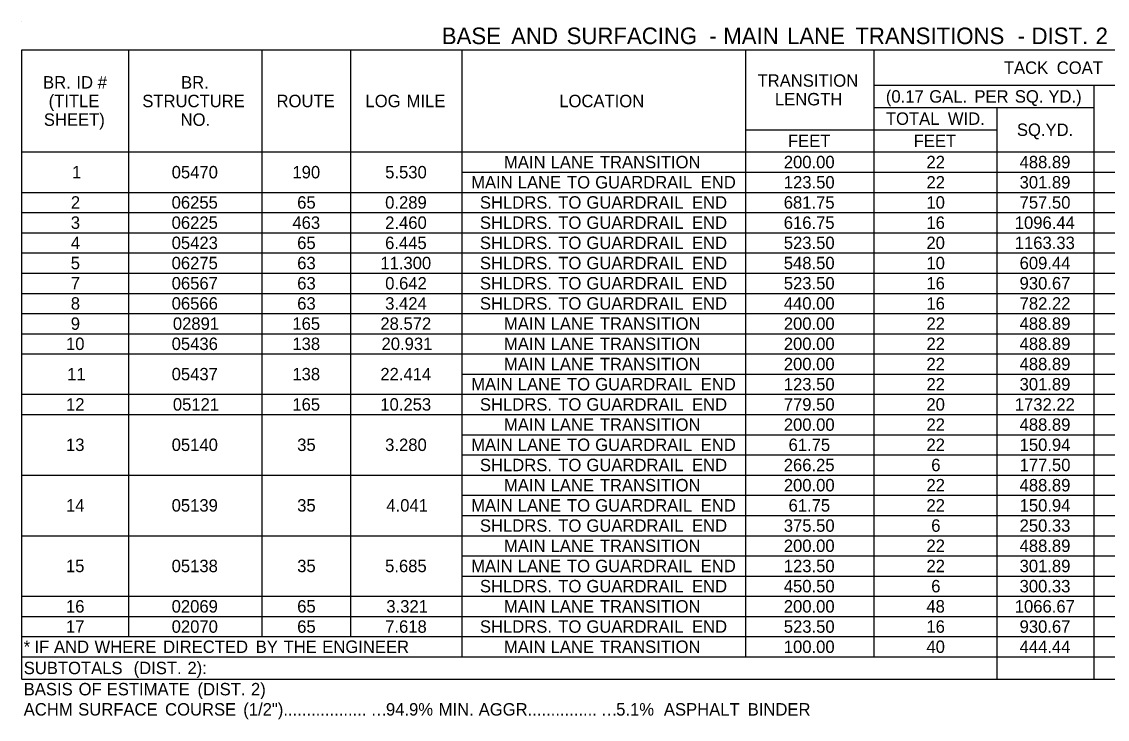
# Model space of a CAD drawing. Extents: x 544250 to 1930787, y -1948365 to 596640.
# Drawn here: x 552201 to 552725, y -1946541 to -1946204 of the extents above; entities that cross this region are included whole.
import ezdxf

# ---------------------------------------------------------------- set-up
doc = ezdxf.new("R2010")
doc.units = 0
doc.layers.add('Default', color=7, linetype='Continuous')

msp = doc.modelspace()

# ---------------------------------------------------------------- linework, layer by layer
at = {"layer": 'Default'}
for p, q in [((552201.23, -1946203.88), (552201.23, -1946203.88)), ((552201.23, -1946217.53), (552997.32, -1946217.53)), ((552201.23, -1946521.24), (552201.23, -1946217.53)), ((552252.9, -1946266.77), (552252.9, -1946217.53)), ((552317.25, -1946266.77), (552317.25, -1946217.53)), ((552360.15, -1946266.77), (552360.15, -1946217.53)), ((552413.78, -1946510.52), (552413.78, -1946217.53)), ((552550.77, -1946510.52), (552550.77, -1946217.53)), ((552612.68, -1946510.52), (552612.68, -1946217.53)), ((552612.68, -1946234.59), (552612.68, -1946217.53)), ((552612.68, -1946234.59), (552997.32, -1946234.59)), ((552718.95, -1946245.32), (552718.95, -1946234.59)), ((552718.95, -1946521.24), (552718.95, -1946234.59)), ((552612.68, -1946245.32), (552718.95, -1946245.32)), ((552672.15, -1946521.24), (552672.15, -1946245.32)), ((552550.77, -1946256.04), (552612.68, -1946256.04)), ((552550.77, -1946256.04), (552672.15, -1946256.04)), ((552672.15, -1946266.77), (552672.15, -1946256.04)), ((552201.23, -1946266.77), (552672.15, -1946266.77)), ((552201.23, -1946266.77), (552413.78, -1946266.77)), ((552252.9, -1946500.77), (552252.9, -1946266.77)), ((552317.25, -1946500.77), (552317.25, -1946266.77)), ((552360.15, -1946500.77), (552360.15, -1946266.77)), ((552413.78, -1946266.77), (552997.32, -1946266.77)), ((552672.15, -1946266.77), (552838.88, -1946266.77)), ((552413.78, -1946276.52), (552997.32, -1946276.52)), ((552201.23, -1946286.27), (552997.32, -1946286.27)), ((552201.23, -1946286.27), (552997.32, -1946286.27)), ((552201.23, -1946296.02), (552997.32, -1946296.02)), ((552201.23, -1946296.02), (552997.32, -1946296.02)), ((552201.23, -1946305.77), (552997.32, -1946305.77)), ((552201.23, -1946305.77), (552997.32, -1946305.77)), ((552201.23, -1946315.52), (552997.32, -1946315.52)), ((552201.23, -1946315.52), (552997.32, -1946315.52)), ((552201.23, -1946325.27), (552997.32, -1946325.27)), ((552201.23, -1946325.27), (552997.32, -1946325.27)), ((552201.23, -1946335.02), (552997.32, -1946335.02)), ((552201.23, -1946335.02), (552997.32, -1946335.02)), ((552201.23, -1946344.77), (552997.32, -1946344.77)), ((552201.23, -1946344.77), (552997.32, -1946344.77)), ((552201.23, -1946354.52), (552997.32, -1946354.52)), ((552201.23, -1946364.27), (552997.32, -1946364.27)), ((552672.15, -1946364.27), (552997.32, -1946364.27)), ((552413.78, -1946374.02), (552672.15, -1946374.02)), ((552672.15, -1946374.02), (552997.32, -1946374.02)), ((552201.23, -1946383.77), (552997.32, -1946383.77)), ((552201.23, -1946383.77), (552997.32, -1946383.77)), ((552201.23, -1946393.52), (552997.32, -1946393.52)), ((552201.23, -1946393.52), (552997.32, -1946393.52)), ((552413.78, -1946403.27), (552997.32, -1946403.27)), ((552413.78, -1946413.02), (552997.32, -1946413.02)), ((552201.23, -1946422.77), (552997.32, -1946422.77)), ((552201.23, -1946422.77), (552997.32, -1946422.77)), ((552413.78, -1946432.52), (552997.32, -1946432.52)), ((552413.78, -1946442.27), (552997.32, -1946442.27)), ((552201.23, -1946452.02), (552997.32, -1946452.02)), ((552201.23, -1946452.02), (552997.32, -1946452.02)), ((552413.78, -1946461.77), (552997.32, -1946461.77)), ((552413.78, -1946471.52), (552997.32, -1946471.52)), ((552201.23, -1946481.27), (552997.32, -1946481.27)), ((552550.77, -1946481.27), (552672.15, -1946481.27)), ((552201.23, -1946491.02), (552550.77, -1946491.02)), ((552413.78, -1946491.02), (552997.32, -1946491.02)), ((552672.15, -1946491.02), (552997.32, -1946491.02)), ((552201.23, -1946500.77), (552997.32, -1946500.77)), ((552413.78, -1946500.77), (552997.32, -1946500.77)), ((552201.23, -1946510.52), (552997.32, -1946510.52)), ((552201.23, -1946521.24), (552997.32, -1946521.24))]:
    msp.add_line(p, q, dxfattribs=at)

# ---------------------------------------------------------------- texts
for s, height, p in [('BASE', 8, (552404.03, -1946214.7)), (' AND', 8, (552434.54, -1946214.7)), (' SURFACING', 8, (552461.31, -1946214.7)), (' MAIN', 8, (552536.93, -1946214.7)), (' LANE', 8, (552567.7, -1946214.7)), (' TRANSITIONS', 8, (552600.68, -1946214.7)), (' DIST.', 8, (552685.75, -1946214.7)), (' 2', 8, (552716.65, -1946214.7)), (' -', 8, (552530.18, -1946214.7)), (' -', 8, (552679, -1946214.7)), ('TACK', 6, (552675.35, -1946229.06)), (' COAT', 6, (552698.63, -1946229.06)), ('TRANSITION', 6, (552556.44, -1946235.28)), ('BR.', 6, (552211.54, -1946236.15)), (' ID', 6, (552225.4, -1946236.15)), (' #', 6, (552235.7, -1946236.15)), ('BR.', 6, (552278.15, -1946236.15)), ('(TITLE', 6, (552214.24, -1946245.15)), ('STRUCTURE', 6, (552259.44, -1946245.15)), ('ROUTE', 6, (552324.24, -1946245.15)), ('LOG', 6, (552367.17, -1946245.15)), (' MILE', 6, (552384.83, -1946245.15)), ('LOCATION', 6, (552460.72, -1946245.15)), ('LENGTH', 6, (552564.81, -1946244.28)), ('(0.17', 6, (552618.38, -1946242.95)), (' GAL.', 6, (552637.1, -1946242.95)), (' PER', 6, (552658.88, -1946242.95)), (' SQ.', 6, (552678.41, -1946242.95)), (' YD.)', 6, (552694.6, -1946242.95)), ('SHEET)', 6, (552211.91, -1946254.15)), ('NO.', 6, (552277.92, -1946254.15)), ('TOTAL', 6, (552618.39, -1946253.68)), (' WID.', 6, (552646.08, -1946253.68)), ('SQ.YD.', 6, (552681.63, -1946259.04)), ('FEET', 6, (552571.1, -1946264.4)), ('FEET', 6, (552631.79, -1946264.4)), ('MAIN', 6, (552434.04, -1946274.64)), (' LANE', 6, (552454.31, -1946274.64)), (' TRANSITION', 6, (552478.09, -1946274.64)), ('200.00', 6, (552569.11, -1946274.64)), ('22', 6, (552637.98, -1946274.64)), ('488.89', 6, (552682.93, -1946274.64)), ('1', 6, (552225.51, -1946279.52)), ('05470', 6, (552273.63, -1946279.52)), ('190', 6, (552331.92, -1946279.52)), ('5.530', 6, (552376.68, -1946279.52)), ('MAIN', 6, (552418.18, -1946284.39)), (' LANE', 6, (552438.46, -1946284.39)), (' TO', 6, (552462.24, -1946284.39)), (' GUARDRAIL', 6, (552475.83, -1946284.39)), (' END', 6, (552526.78, -1946284.39)), ('123.50', 6, (552569.11, -1946284.39)), ('22', 6, (552637.98, -1946284.39)), ('301.89', 6, (552682.93, -1946284.39)), ('2', 6, (552224.96, -1946294.14)), ('06255', 6, (552273.6, -1946294.14)), ('65', 6, (552334.21, -1946294.14)), ('0.289', 6, (552376.67, -1946294.14)), ('SHLDRS.', 6, (552422.41, -1946294.14)), (' TO', 6, (552458.01, -1946294.14)), (' GUARDRAIL', 6, (552471.61, -1946294.14)), (' END', 6, (552522.56, -1946294.14)), ('681.75', 6, (552569.08, -1946294.14)), ('10', 6, (552637.96, -1946294.14)), ('757.50', 6, (552682.94, -1946294.14)), ('3', 6, (552224.93, -1946303.89)), ('06225', 6, (552273.6, -1946303.89)), ('463', 6, (552331.9, -1946303.89)), ('2.460', 6, (552376.68, -1946303.89)), ('SHLDRS.', 6, (552422.41, -1946303.89)), (' TO', 6, (552458.01, -1946303.89)), (' GUARDRAIL', 6, (552471.61, -1946303.89)), (' END', 6, (552522.56, -1946303.89)), ('616.75', 6, (552569.08, -1946303.89)), ('16', 6, (552637.95, -1946303.89)), ('1096.44', 6, (552680.61, -1946303.89)), ('4', 6, (552224.94, -1946313.64)), ('05423', 6, (552273.62, -1946313.64)), ('65', 6, (552334.21, -1946313.64)), ('6.445', 6, (552376.65, -1946313.64)), ('SHLDRS.', 6, (552422.41, -1946313.64)), (' TO', 6, (552458.01, -1946313.64)), (' GUARDRAIL', 6, (552471.61, -1946313.64)), (' END', 6, (552522.56, -1946313.64)), ('523.50', 6, (552569.11, -1946313.64)), ('20', 6, (552637.96, -1946313.64)), ('1163.33', 6, (552680.6, -1946313.64)), ('5', 6, (552224.9, -1946323.39)), ('06275', 6, (552273.6, -1946323.39)), ('63', 6, (552334.23, -1946323.39)), ('11.300', 6, (552374.35, -1946323.39)), ('SHLDRS.', 6, (552422.41, -1946323.39)), (' TO', 6, (552458.01, -1946323.39)), (' GUARDRAIL', 6, (552471.61, -1946323.39)), (' END', 6, (552522.56, -1946323.39)), ('548.50', 6, (552569.11, -1946323.39)), ('10', 6, (552637.96, -1946323.39)), ('609.44', 6, (552682.94, -1946323.39)), ('7', 6, (552224.93, -1946333.14)), ('06567', 6, (552273.62, -1946333.14)), ('63', 6, (552334.23, -1946333.14)), ('0.642', 6, (552376.7, -1946333.14)), ('SHLDRS.', 6, (552422.41, -1946333.14)), (' TO', 6, (552458.01, -1946333.14)), (' GUARDRAIL', 6, (552471.61, -1946333.14)), (' END', 6, (552522.56, -1946333.14)), ('523.50', 6, (552569.11, -1946333.14)), ('16', 6, (552637.95, -1946333.14)), ('930.67', 6, (552682.93, -1946333.14)), ('8', 6, (552224.92, -1946342.89)), ('06566', 6, (552273.62, -1946342.89)), ('63', 6, (552334.23, -1946342.89)), ('3.424', 6, (552376.69, -1946342.89)), ('SHLDRS.', 6, (552422.41, -1946342.89)), (' TO', 6, (552458.01, -1946342.89)), (' GUARDRAIL', 6, (552471.61, -1946342.89)), (' END', 6, (552522.56, -1946342.89)), ('440.00', 6, (552569.11, -1946342.89)), ('16', 6, (552637.95, -1946342.89)), ('782.22', 6, (552682.96, -1946342.89)), ('9', 6, (552224.92, -1946352.64)), ('02891', 6, (552274.2, -1946352.64)), ('165', 6, (552331.88, -1946352.64)), ('28.572', 6, (552374.37, -1946352.64)), ('MAIN', 6, (552434.04, -1946352.64)), (' LANE', 6, (552454.31, -1946352.64)), (' TRANSITION', 6, (552478.09, -1946352.64)), ('200.00', 6, (552569.11, -1946352.64)), ('22', 6, (552637.98, -1946352.64)), ('488.89', 6, (552682.93, -1946352.64)), ('10', 6, (552222.61, -1946362.39)), ('05436', 6, (552273.62, -1946362.39)), ('138', 6, (552331.9, -1946362.39)), ('20.931', 6, (552374.92, -1946362.39)), ('MAIN', 6, (552434.04, -1946362.39)), (' LANE', 6, (552454.31, -1946362.39)), (' TRANSITION', 6, (552478.09, -1946362.39)), ('200.00', 6, (552569.11, -1946362.39)), ('22', 6, (552637.98, -1946362.39)), ('488.89', 6, (552682.93, -1946362.39)), ('05437', 6, (552273.62, -1946377.02)), ('138', 6, (552331.9, -1946377.02)), ('22.414', 6, (552374.36, -1946377.02)), ('MAIN', 6, (552434.04, -1946372.14)), (' LANE', 6, (552454.31, -1946372.14)), (' TRANSITION', 6, (552478.09, -1946372.14)), ('200.00', 6, (552569.11, -1946372.14)), ('22', 6, (552637.98, -1946372.14)), ('488.89', 6, (552682.93, -1946372.14)), ('11', 6, (552223.18, -1946377.02)), ('MAIN', 6, (552418.18, -1946381.89)), (' LANE', 6, (552438.46, -1946381.89)), (' TO', 6, (552462.24, -1946381.89)), (' GUARDRAIL', 6, (552475.83, -1946381.89)), (' END', 6, (552526.78, -1946381.89)), ('123.50', 6, (552569.11, -1946381.89)), ('22', 6, (552637.98, -1946381.89)), ('301.89', 6, (552682.93, -1946381.89)), ('12', 6, (552222.63, -1946391.64)), ('05121', 6, (552274.2, -1946391.64)), ('165', 6, (552331.88, -1946391.64)), ('10.253', 6, (552374.34, -1946391.64)), ('SHLDRS.', 6, (552422.41, -1946391.64)), (' TO', 6, (552458.01, -1946391.64)), (' GUARDRAIL', 6, (552471.61, -1946391.64)), (' END', 6, (552522.56, -1946391.64)), ('779.50', 6, (552569.11, -1946391.64)), ('20', 6, (552637.96, -1946391.64)), ('1732.22', 6, (552680.63, -1946391.64)), ('MAIN', 6, (552434.04, -1946401.39)), (' LANE', 6, (552454.31, -1946401.39)), (' TRANSITION', 6, (552478.09, -1946401.39)), ('200.00', 6, (552569.11, -1946401.39)), ('22', 6, (552637.98, -1946401.39)), ('488.89', 6, (552682.93, -1946401.39)), ('13', 6, (552222.6, -1946411.14)), ('05140', 6, (552273.63, -1946411.14)), ('35', 6, (552334.21, -1946411.14)), ('3.280', 6, (552376.68, -1946411.14)), ('MAIN', 6, (552418.18, -1946411.14)), (' LANE', 6, (552438.46, -1946411.14)), (' TO', 6, (552462.24, -1946411.14)), (' GUARDRAIL', 6, (552475.83, -1946411.14)), (' END', 6, (552526.78, -1946411.14)), ('61.75', 6, (552571.41, -1946411.14)), ('22', 6, (552637.98, -1946411.14)), ('150.94', 6, (552682.94, -1946411.14)), ('SHLDRS.', 6, (552422.41, -1946420.89)), (' TO', 6, (552458.01, -1946420.89)), (' GUARDRAIL', 6, (552471.61, -1946420.89)), (' END', 6, (552522.56, -1946420.89)), ('266.25', 6, (552569.08, -1946420.89)), ('6', 6, (552640.28, -1946420.89)), ('177.50', 6, (552682.94, -1946420.89)), ('MAIN', 6, (552434.04, -1946430.64)), (' LANE', 6, (552454.31, -1946430.64)), (' TRANSITION', 6, (552478.09, -1946430.64)), ('200.00', 6, (552569.11, -1946430.64)), ('22', 6, (552637.98, -1946430.64)), ('488.89', 6, (552682.93, -1946430.64)), ('14', 6, (552222.61, -1946440.39)), ('05139', 6, (552273.61, -1946440.39)), ('35', 6, (552334.21, -1946440.39)), ('4.041', 6, (552377.25, -1946440.39)), ('MAIN', 6, (552418.18, -1946440.39)), (' LANE', 6, (552438.46, -1946440.39)), (' TO', 6, (552462.24, -1946440.39)), (' GUARDRAIL', 6, (552475.83, -1946440.39)), (' END', 6, (552526.78, -1946440.39)), ('61.75', 6, (552571.41, -1946440.39)), ('22', 6, (552637.98, -1946440.39)), ('150.94', 6, (552682.94, -1946440.39)), ('SHLDRS.', 6, (552422.41, -1946450.14)), (' TO', 6, (552458.01, -1946450.14)), (' GUARDRAIL', 6, (552471.61, -1946450.14)), (' END', 6, (552522.56, -1946450.14)), ('375.50', 6, (552569.11, -1946450.14)), ('6', 6, (552640.28, -1946450.14)), ('250.33', 6, (552682.93, -1946450.14)), ('MAIN', 6, (552434.04, -1946459.89)), (' LANE', 6, (552454.31, -1946459.89)), (' TRANSITION', 6, (552478.09, -1946459.89)), ('200.00', 6, (552569.11, -1946459.89)), ('22', 6, (552637.98, -1946459.89)), ('488.89', 6, (552682.93, -1946459.89)), ('15', 6, (552222.57, -1946469.64)), ('05138', 6, (552273.61, -1946469.64)), ('35', 6, (552334.21, -1946469.64)), ('5.685', 6, (552376.65, -1946469.64)), ('MAIN', 6, (552418.18, -1946469.64)), (' LANE', 6, (552438.46, -1946469.64)), (' TO', 6, (552462.24, -1946469.64)), (' GUARDRAIL', 6, (552475.83, -1946469.64)), (' END', 6, (552526.78, -1946469.64)), ('123.50', 6, (552569.11, -1946469.64)), ('22', 6, (552637.98, -1946469.64)), ('301.89', 6, (552682.93, -1946469.64)), ('SHLDRS.', 6, (552422.41, -1946479.39)), (' TO', 6, (552458.01, -1946479.39)), (' GUARDRAIL', 6, (552471.61, -1946479.39)), (' END', 6, (552522.56, -1946479.39)), ('450.50', 6, (552569.11, -1946479.39)), ('6', 6, (552640.28, -1946479.39)), ('300.33', 6, (552682.93, -1946479.39)), ('16', 6, (552222.6, -1946489.14)), ('02069', 6, (552273.61, -1946489.14)), ('65', 6, (552334.21, -1946489.14)), ('3.321', 6, (552377.25, -1946489.14)), ('MAIN', 6, (552434.04, -1946489.14)), (' LANE', 6, (552454.31, -1946489.14)), (' TRANSITION', 6, (552478.09, -1946489.14)), ('200.00', 6, (552569.11, -1946489.14)), ('48', 6, (552637.94, -1946489.14)), ('1066.67', 6, (552680.6, -1946489.14)), ('17', 6, (552222.6, -1946498.89)), ('02070', 6, (552273.63, -1946498.89)), ('65', 6, (552334.21, -1946498.89)), ('7.618', 6, (552376.67, -1946498.89)), ('SHLDRS.', 6, (552422.41, -1946498.89)), (' TO', 6, (552458.01, -1946498.89)), (' GUARDRAIL', 6, (552471.61, -1946498.89)), (' END', 6, (552522.56, -1946498.89)), ('523.50', 6, (552569.11, -1946498.89)), ('16', 6, (552637.95, -1946498.89)), ('930.67', 6, (552682.93, -1946498.89)), ('*', 6, (552202.2, -1946508.64)), (' IF', 6, (552205.17, -1946508.64)), (' AND', 6, (552214.57, -1946508.64)), (' WHERE', 6, (552234.15, -1946508.64)), (' DIRECTED', 6, (552267.24, -1946508.64)), (' BY', 6, (552311.97, -1946508.64)), (' THE', 6, (552325.42, -1946508.64)), (' ENGINEER', 6, (552344.07, -1946508.64)), ('MAIN', 6, (552434.04, -1946508.64)), (' LANE', 6, (552454.31, -1946508.64)), (' TRANSITION', 6, (552478.09, -1946508.64)), ('100.00', 6, (552569.11, -1946508.64)), ('40', 6, (552637.96, -1946508.64)), ('444.44', 6, (552682.94, -1946508.64)), ('SUBTOTALS', 6, (552202.2, -1946518.88)), (' (DIST.', 6, (552253.03, -1946518.88)), (' 2):', 6, (552279, -1946518.88)), (' (DIST.', 6, (552283.86, -1946529.12)), (' 2)', 6, (552309.67, -1946529.12)), ('BASIS', 6, (552202.2, -1946529.12)), (' OF', 6, (552226.47, -1946529.12)), (' ESTIMATE', 6, (552240.05, -1946529.12)), ('ACHM', 6, (552202.2, -1946538.87)), (' SURFACE', 6, (552226.26, -1946538.87)), (' COURSE', 6, (552268.2, -1946538.87)), (' (1/2")..................', 6, (552305.96, -1946538.87)), ('94.9%', 6, (552377.06, -1946538.87)), (' MIN.', 6, (552400.3, -1946538.87)), (' AGGR...............', 6, (552419.59, -1946538.87)), ('5.1%', 6, (552488.19, -1946538.87)), ('  ASPHALT', 6, (552506.77, -1946538.87)), (' BINDER', 6, (552549.46, -1946538.87)), ('…', 6, (552369.66, -1946538.87)), ('…', 6, (552480.79, -1946538.87))]:
    msp.add_text(s, height=height, dxfattribs=at).set_placement(p)

doc.saveas('drawing.dxf')
